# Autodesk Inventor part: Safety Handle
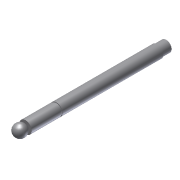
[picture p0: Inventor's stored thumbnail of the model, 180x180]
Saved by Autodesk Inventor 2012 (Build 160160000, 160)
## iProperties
Shininess: 77.0
Length Units: 11269
Angle Units: 11279
Time Units: 11290
Mass Units: 11283
Length Display Precision: 3
Angle Display Precision: 2
Created: 2002-02
Part Number: Safety Handle
Document SubType Name: Modeling
Designer: ***
Density: 1 g/cm^3
Material: Default
Density: 0.0
Volumn: 0.0
Area: 0.0
PropertySet Name: Model Information
Control State: 0
Master: False
Checked Out: False
Author: ***
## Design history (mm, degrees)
sketch "Sketch1"
  geometry: L1 (0, 205)-(8, 205); L2 (8, 205)-(8, 192); L3 (8, 192)-(9, 192); L4 (9, 192)-(9, 45); L5 (9, 45)-(8, 45); L6 (8, 45)-(8, 43); L7 (8, 43)-(9, 43); L8 (9, 43)-(9, 0); L9 (9, 0)-(0, 0); L10 (0, 0)-(0, 205)
  constraints: 20 end point, 7 parallel, 1 collinear, 1 horizontal, 1 perpendicular
  dimensions: "d0" = 13 distance of L1.end L2.end; "d1" = 2 distance of L4.end L7.end; "d2" = 43 distance of L7.end L8.end; "d3" = 205 distance of L9.end L1.start; "d4" = 16 diameter of L2 L10; "d5" = 18 diameter of L4 L10; "d6" = 16 diameter of L6.end L10
revolve "Revolution1" sketch "Sketch1" stored, may be unused: angle "d7" = 90 deg
sketch "Sketch2"
  geometry: L1 (0, 1)-(0, -17); L2 (-9, 0)-(9, 0) reference; A1 r 9 centre (0, -8) between (0, -17) and (0, 1)
  constraints: 2 end point, 2 point on circle, 1 centre point, 1 midpoint, 1 vertical
  dimensions: "d8" = 9 radius of A1; "d9" = 1 distance from line of L2 L1.start
revolve "Revolution2" sketch "Sketch2" stored, may be unused: angle "d10" = 90 deg
body "Solid1"
